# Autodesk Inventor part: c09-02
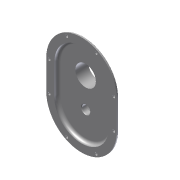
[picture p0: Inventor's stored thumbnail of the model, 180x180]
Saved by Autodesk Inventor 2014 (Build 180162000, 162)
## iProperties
Created: 2010-12
Part Number: c09-02
Document SubType Name: Modeling
Designer: Thom Tremblay
Density: 7.25 g/cm^3
Material: Iron, Cast
Mass: 515.624 g
Surface Area: 438.513 cm^2
Volume: 71.1205 cm^3
Appearance: Steel
Author: Thom Tremblay
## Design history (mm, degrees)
sketch "Sketch1"
  geometry: L1 (-50, -50)-(-50, 0); L2 (50, 0)-(50, -50); L3 (-60, 0)-(-60, -50); L4 (60, -50)-(60, 0); A1 r 50 centre (0, 0) between (50, 0) and (-50, 0); A2 r 50 centre (0, -50) between (-50, -50) and (50, -50); A3 r 60 centre (0, -50) between (-60, -50) and (60, -50); A4 r 60 centre (0, 0) between (60, 0) and (-60, 0); 1 further point
  constraints: 8 end point, 8 point on circle, 4 centre point, 4 tangent, 2 parallel, 1 coincident, 1 vertical, 3 other
  dimensions: "d0" = 50 distance of L2.start L2.end; "d1" = 50 radius of A1; "d2" = 10 radial gap between concentric circles of A4 A1
extrude "Extrusion1" new body sketch "Sketch1" distance "d3" = 10; taper "d4" = -2 deg
extrude "Extrusion2" join sketch "Sketch1" distance "d5" = 3; taper "d6" = -2 deg
fillet "Fillet1" dims "d7" = 8
shell "Shell2" dims "d128" = 3
fillet "Fillet2" dims "d9" = 1.5, "d10" = 1
sketch "Sketch7"
  geometry: C1 r 22.5 at (0, 0); 1 further point
  constraints: 1 centre point, 1 coincident
  dimensions: "d63" = 45 diameter of C1
extrude "Extrusion8" join sketch "Sketch7" distance "d64" = 19; taper "d65" = -2 deg
hole "Hole3" diameter "d68" = 35; stored, may be unused: countersink angle "d72" = 82 deg, drill point angle "d74" = 118 deg; dims "d66" = 10, "d67" = 10, "d69" = 19.05, "d70" = 9.525, "d71" = 6.35, "d73" = 25.4
fillet "Fillet11" dims "d75" = 3
sketch "Sketch8"
  geometry: C1 r 12.5 at (0, -50); A1 r 60 centre (0, -50) between (-60, -50) and (60, -50) reference; 1 further point
  constraints: 1 centre point, 1 coincident
  dimensions: "d76" = 25 diameter of C1
extrude "Extrusion9" join sketch "Sketch8" distance "d77" = 12; taper "d78" = -2 deg; dims "d89" = 8, "d90" = -2 deg
fillet "Fillet12" dims "d79" = 3
hole "Hole4" diameter "d82" = 14; stored, may be unused: countersink angle "d86" = 82 deg, drill point angle "d88" = 118 deg; dims "d80" = 10, "d81" = 10, "d83" = 19.05, "d84" = 9.525, "d85" = 6.35, "d87" = 8
sketch "Sketch9" dims "d91" = 45
  geometry: L1 (0, 0)-(0, 22.5); C1 r 4 at (0, 22.5); 1 further point
  constraints: 2 end point, 1 centre point, 1 coincident, 1 vertical, 1 vertical alignment, 2 other
  dimensions: "d92" = 8 diameter of C1
extrude "Extrusion10" join sketch "Sketch9" stored distance "d95" = 0; taper "d96" = 2 deg
fillet "Fillet13" dims "d97" = 3
hole "Hole5" diameter "d100" = 3.242; stored, may be unused: countersink angle "d104" = 82 deg, drill point angle "d106" = 118 deg; dims "d98" = 10, "d99" = 10, "d101" = 8, "d102" = 9.525, "d103" = 6.35, "d105" = 10
pattern_circular "Circular Pattern1" dims "d108" = 360 deg
sketch "Sketch10"
  geometry: L1 (-55, -50.8)-(-55, 0); L2 (55, 0)-(55, -50.8); A1 r 55 centre (0, 0) between (55, 0) and (-55, 0); A2 r 55 centre (0, -50.8) between (-55, -50.8) and (55, -50.8); 9 further points
  constraints: 8 point on circle, 5 coincident, 4 end point, 4 tangent, 2 centre point, 2 horizontal alignment, 2 vertical alignment, 1 parallel, 1 vertical
  dimensions: "d118" = 55 radius of A1; "d120" = 50 distance of point (25, 48.99) point (-25, 48.99)
hole "Hole7" sketch "Sketch10" at (-55, -50.8), (-55, 0), (-25, 48.99), (25, 48.99), (55, 0), (55, -50.8), (25, -99.79), (-25, -99.79) diameter "d121" = 4.5; stored, may be unused: countersink angle "d125" = 82 deg, drill point angle "d127" = 118 deg; dims "d122" = 19.05, "d123" = 7.0866, "d124" = 6.35, "d126" = 25.4
chamfer "Chamfer1" distance "d129" = 1; stored, may be unused: second distance "d130" = 2, angle "d131" = 45 deg
body "Solid1"
